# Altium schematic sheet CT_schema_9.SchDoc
size 278 x 170 mm
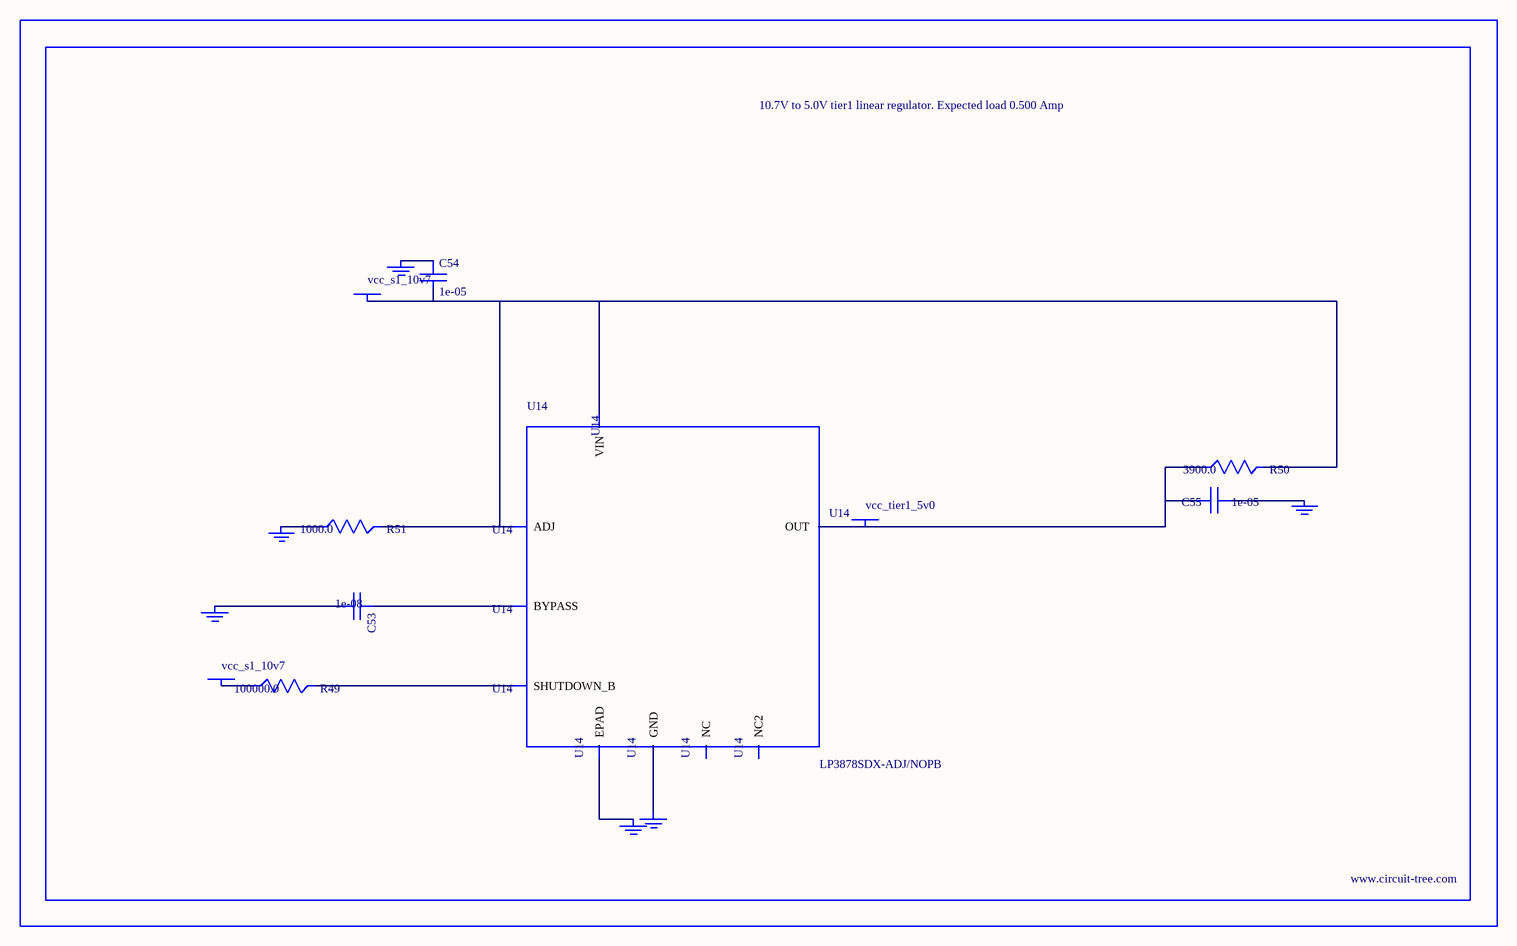
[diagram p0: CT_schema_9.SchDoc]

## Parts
BORDER8  (no value)
C53  1e-08  [C0402]
C54  1e-05  [C1206]
C55  1e-05  [C1210]
GND_INSTANCE_8_0  (no value)
GND_INSTANCE_8_1  (no value)
GND_INSTANCE_8_2  (no value)
GND_INSTANCE_8_3  (no value)
GND_INSTANCE_8_4  (no value)
GND_INSTANCE_8_5  (no value)
POWER_INSTANCE_8_0  vcc_s1_10v7
POWER_INSTANCE_8_1  vcc_s1_10v7
POWER_INSTANCE_8_2  vcc_tier1_5v0
R49  100000.0  [R0603]
R50  3900.0  [R0603]
R51  1000.0  [R0603]
U14  LP3878SDX-ADJ/NOPB  [WSON-8]

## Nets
NetC53_1: C53.1 U14.1(BYPASS)
NetC53_2: C53.2 GND_INSTANCE_8_0.0(GND)
NetC54_1: C54.1 GND_INSTANCE_8_1.0(GND)
NetC54_2: C54.2 POWER_INSTANCE_8_0.0(PWR) R50.2 R51.2 U14.4(VIN) U14.6(ADJ)
NetC55_1: C55.1 GND_INSTANCE_8_2.0(GND)
NetC55_2: C55.2 POWER_INSTANCE_8_2.0(PWR) R50.1 U14.5(OUT)
NetGND_INSTANCE_8_3_0: GND_INSTANCE_8_3.0(GND) R51.1
NetGND_INSTANCE_8_4_0: GND_INSTANCE_8_4.0(GND) U14.PAD(EPAD)
NetGND_INSTANCE_8_5_0: GND_INSTANCE_8_5.0(GND) U14.3(GND)
NetPOWER_INSTANCE_8_1_0: POWER_INSTANCE_8_1.0(PWR) R49.1
NetR49_2: R49.2 U14.8(SHUTDOWN_B)

Not connected (* = marked no-connect by the designer): U14 2(NC) 7(NC2)

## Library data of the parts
BORDER8 = BORDER_PAGE8
C53 = C0402C103K3RAC
C54 = C1206C106K3RACTU
C55 = GRM32DR61E106MA12L
GND_INSTANCE_8_0-GND_INSTANCE_8_5 = GND
POWER_INSTANCE_8_0-POWER_INSTANCE_8_2 = PWR
R49 = RC0603JR-07100KL
R50 = RC0603JR-073K9L
R51 = RC0603JR-071KL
